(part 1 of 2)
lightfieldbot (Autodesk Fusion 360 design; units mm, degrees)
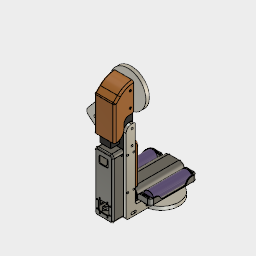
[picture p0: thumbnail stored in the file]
parameter "servohole_1" = 2.8
parameter "d75_1" = 4.75
parameter "d76_1" = 0
parameter "d77_1" = 0
parameter "d78_1" = 0
parameter "d79_1" = 0
parameter "d89_1" = 0
parameter "d90_1" = 0
parameter "d91_1" = 0
parameter "d101_1" = 0
parameter "d102_1" = 0
parameter "d103_1" = 0
parameter "d129_1" = 0
parameter "d130_1" = 0
parameter "d131_1" = 0
parameter "d154_1" = 0
parameter "d155_1" = 0
parameter "d156_1" = 0
parameter "d166_1" = 0
parameter "d167_1" = 0
parameter "d168_1" = 0
parameter "d510" = 25
sketch "Sketch1"
  line L1 (16.7662, -74.21) -> (-16.8338, -74.21)
  line L2 (16.7662, 16.1) -> (16.7662, -74.21)
  line L3 (-16.7662, 16.1) -> (16.7662, 16.1)
  line L4 (-16.7662, -74.21) -> (-16.7662, 16.1)
  line L5 (16.7662, 0) -> (0, 0)
  line L6 (-16.7662, 0) -> (0, 0)
  line L7 (16.7662, -74.21) -> (-16.7662, -74.21)
  line L8 (16.7662, -78.09) -> (16.7662, -74.21)
  line L9 (-16.7662, -78.09) -> (16.7662, -78.09)
  line L10 (-16.7662, -74.21) -> (-16.7662, -78.09)
  circle C1 centre (0, 0) radius 32.5
  circle C2 centre (0, 0) radius 6.325
  point P3 (16.7662, -74.21)
  point P4 (16.7662, 16.1)
  point P2 (-16.8338, -74.21)
  point P1 (0, 0)
  point P7 (-16.7662, -74.21)
  point P14 (-16.7662, -78.09)
  dimension "d1_1" distance P3 P4 = 90.31
  dimension "d2_1" distance P2 P3 = 33.6
  dimension "d3_1" diameter C1 = 65
  dimension "d4_1" distance P1 L1 = 74.21
  dimension "d5_1" distance P7 P14 = 3.88
  dimension "d25_1" diameter C2 = 12.65
  dimension "d93_1" OffsetX = 0
  dimension "d94_1" OffsetY = 0
  dimension "d95_1" OffsetZ = 0
  dimension "d96_1" AngleZ = 0
  dimension "d105_1" OffsetX = 0
  dimension "d106_1" OffsetY = 0
  dimension "d107_1" OffsetZ = 0
  dimension "d108_1" AngleZ = 0
  dimension "d158_1" OffsetX = 0
  dimension "d159_1" OffsetY = 0
  dimension "d160_1" OffsetZ = 0
  dimension "d161_1" AngleZ = 0
extrude "Extrude1" sketch "Sketch1" profile of L1 L2 L3 L4 C1 L7 blind 16.7 named "d6_1"
extrude "Extrude2" sketch "Sketch1" profile of L2 L3 L4 C1 blind -6.4 named "d9_1" from offset -8 named "d8_1"
extrude "Extrude3" sketch "Sketch1" profile of L1 L7 L8 L9 L10 blind 3.25 named "d11_1"
sketch "Sketch2" plane through (0, 0, 16.7) normal (0, 0, 1) x axis (-1, 0, 0)
  line L1 (-16.7662, 74.21) -> (16.7662, 74.21)
  line L2 (-16.7662, -16.1) -> (-16.7662, 74.21)
  line L3 (16.7662, -16.1) -> (-16.7662, -16.1)
  line L4 (16.7662, 74.21) -> (16.7662, -16.1)
  line L5 (-9.8, 68.21) -> (9.8, 68.21)
  line L6 (-9.8, 27.86) -> (-9.8, 68.21)
  line L7 (9.8, 27.86) -> (-9.8, 27.86)
  line L8 (9.8, 68.21) -> (9.8, 27.86)
  line L9 (0, 68.21) -> (0, 74.21)
  line L10 (-6.85, 6.9425) -> (6.85, 6.9425)
  line L11 (-6.85, -6.9075) -> (-6.85, 6.9425)
  line L12 (6.85, -6.9075) -> (-6.85, -6.9075)
  line L13 (6.85, 6.9425) -> (6.85, -6.9075)
  line L14 (0, 0) -> (0, -6.9075)
  point P6 (9.8, 68.21)
  point P7 (-9.8, 68.21)
  point P8 (-9.8, 27.86)
  point P14 (-6.85, -6.9075)
  point P15 (6.85, -6.9075)
  point P13 (-6.85, 6.9425)
  dimension "d13_1" distance P6 P7 = 19.6
  dimension "d14_1" distance P7 P8 = 40.35
  dimension "d15_1" distance L1 L5 = 6
  dimension "d16_1" distance P14 P15 = 13.7
  dimension "d17_1" distance P13 P14 = 13.85
extrude "Extrude4" sketch "Sketch2" profile of L10 L11 L12 L13 blind 13.07 named "d18_1"
extrude "Extrude5" sketch "Sketch2" profile of L5 L6 L7 L8 blind 16.07 named "d20_1"
sketch "Sketch3" plane through (0, 0, -14.4) normal (0, 0, -1) x axis (1, 0, 0)
  circle C1 centre (0, 0) radius 32.5
  circle C2 centre (0, 0) radius 12.65
  dimension "d22_1" diameter C2 = 25.3
extrude "Extrude6" add sketch "Sketch3" profile of C2 along normal blind 6.2 named "d23_1"
extrude "Extrude7" add sketch "Sketch1" profile of C2 to an object
sketch "Sketch4" plane through (-16.7662, 0, 0) normal (-1, 0, 0) x axis (0, -1, 0)
  line L1 (78.09, 0) -> (-16.1, 0)
  line L2 (78.09, 3.25) -> (78.09, 0)
  line L3 (74.21, 3.25) -> (78.09, 3.25)
  line L4 (74.21, 16.7) -> (74.21, 3.25)
  line L5 (-16.1, 16.7) -> (74.21, 16.7)
  line L6 (-16.1, 0) -> (-16.1, 16.7)
  line L7 (74.21, 16.7) -> (-16.1, 16.7)
  circle C1 centre (-13.1, 5.8006) radius 1.4
  circle C2 centre (-13.1, 13.7) radius 1.4
  circle C3 centre (13.8494, 13.7) radius 1.4
  circle C4 centre (13.8494, 5.8006) radius 1.4
  circle C5 centre (70.9994, 5.8006) radius 1.4
  circle C6 centre (70.9994, 13.7) radius 1.4
  circle C7 centre (44.05, 13.7) radius 1.4
  circle C8 centre (44.05, 5.8006) radius 1.4
  point P8 (-13.1, 5.8006)
  point P9 (-13.1, 13.7)
  point P10 (13.8494, 13.7)
  point P11 (13.8494, 5.8006)
  point P14 (44.05, 13.7)
  point P15 (44.05, 5.8006)
  point P12 (70.9994, 13.7)
  point P13 (70.9994, 5.8006)
  dimension "d28_1" diameter C1 = 2.8 (= "servohole_1")
  dimension "d29_1" diameter C2 = 2.8 (= "servohole_1")
  dimension "d31_1" distance P8 P9 = 7.8994
  dimension "d32_1" diameter C4 = 2.8 (= "servohole_1")
  dimension "d33_1" diameter C3 = 2.8 (= "servohole_1")
  dimension "d34_1" distance P10 P11 = 7.8994
  dimension "d35_1" distance P9 P10 = 26.9494
  dimension "d36_1" diameter C8 = 2.8 (= "servohole_1")
  dimension "d37_1" diameter C7 = 2.8 (= "servohole_1")
  dimension "d38_1" distance P14 P15 = 7.8994
  dimension "d39_1" diameter C5 = 2.8 (= "servohole_1")
  dimension "d40_1" diameter C6 = 2.8 (= "servohole_1")
  dimension "d41_1" distance P12 P13 = 7.8994
  dimension "d42_1" distance P12 P14 = 26.9494
  dimension "d43_1" distance P9 P12 = 84.0994
  dimension "d44_1" distance P9 L7 = 3
  dimension "d50_1" distance L6 P9 = 3
extrude "Extrude8" sketch "Sketch4" profile of C1 C2 C3 C4 C5 C6 C7 C8 blind -7 named "d45_1"
extrude "Extrude9" sketch "Sketch4" profile of C1 C2 C3 C4 C5 C6 C7 C8 blind 7 named "d48_1"
joint_origin "JointOrigin5" OffsetX 0 named "d170_1" OffsetY 0 named "d171_1" OffsetZ 0 named "d172_1" AngleZ 0 named "d173_1"
sketch "Sketch2"
  line L1 (-72, 0) -> (0, 0)
  line L2 (-72, 136) -> (-72, 0)
  line L3 (0, 136) -> (-72, 136)
  line L4 (0, 0) -> (0, 136)
  line L5 (-52, 136) -> (0, 136)
  line L6 (-72, 33) -> (-72, 0)
  line L7 (-72, 103) -> (-72, 136)
  line L8 (-52, 103) -> (-72, 103)
  line L9 (-52, 0) -> (-52, 103)
  point P2 (0, 0)
  point P3 (-72, 0)
  point P4 (-72, 136)
  point P8 (-72, 103)
  dimension "d53_1" distance P2 P3 = 72
  dimension "d59_1" distance P4 P8 = 33
  dimension "d60_1" distance L4 L9 = 52
  dimension "d81_1" OffsetX = 0
  dimension "d82_1" OffsetY = 0
  dimension "d83_1" OffsetZ = 0
  dimension "d84_1" AngleZ = 0
  dimension "d72" OffsetX = 0
  dimension "d73" OffsetY = 0
  dimension "d74" OffsetZ = 0
  dimension "d85" AngleZ = 0
extrude "Extrude1" new body sketch "Sketch2" profile of L1 L2 L3 L4 L5 L7 L8 L9 blind 107 named "d57_1"
sketch "Sketch3" plane through (0, 0, 0) normal (0, 0, -1) x axis (1, 0, 0)
  line L1 (-52, 0) -> (0, 0)
  line L2 (-52, -103) -> (-52, 0)
  line L3 (-72, -103) -> (-52, -103)
  line L4 (-72, -136) -> (-72, -103)
  line L5 (0, -136) -> (-72, -136)
  line L6 (0, 0) -> (0, -136)
  circle C1 centre (-18, -53.2) radius 2.5
  point P8 (-18, -53.2)
  dimension "d61_1" diameter C1 = 5
  dimension "d62_1" distance L1 P8 = 53.2
  dimension "d63_1" distance L6 P8 = 18
  dimension "d80_1" AngleZ = 0
  dimension "d92_1" AngleZ = 0
  dimension "d104_1" AngleZ = 0
  dimension "d132_1" AngleZ = 0
  dimension "d157_1" AngleZ = 0
  dimension "d169_1" AngleZ = 0
extrude "Extrude2" cut sketch "Sketch3" profile of C1 against normal blind 12 named "d64_1"
sketch "Sketch4" plane through (-52, 0, 0) normal (-1, 0, 0) x axis (0, -1, 0)
  line L1 (0, 0) -> (-103, 0)
  line L2 (0, 107) -> (0, 0)
  line L3 (-103, 107) -> (0, 107)
  line L4 (-103, 0) -> (-103, 107)
  line L5 (-55.7, 0) -> (-50.7, 0)
  line L6 (-53.2, 42.5) -> (-53.2, 0)
  circle C1 centre (-53.2, 42.5) radius 37.25
  point P6 (-53.2, 42.5)
  dimension "d66_1" distance L1 P6 = 42.5
  dimension "d70_1" diameter C1 = 74.5
extrude "Extrude3" add sketch "Sketch4" profile of C1 along normal blind 95 (= "147 mm - 52 mm") named "d68_1"
copy_paste "CopyPaste1"
sketch "moveplate" plane through (0, -65.568, 162.694) normal (0, 1, 0) x axis (1, 0, 0)
  line L1 (-104, 2.375) -> (-111, 2.375)
  line L2 (-104, -2.375) -> (-22.0772, -2.375)
  line L3 (-122.0642, -15) -> (-122.064, 15)
  line L4 (-22.0772, -2.375) -> (-22.0772, 2.375)
  line L5 (-122.064, 0.9248) -> (-530.5103, 3.462)
  line L6 (-22.0772, 2.375) -> (-104, 2.375)
  line L7 (14.9358, -15) -> (-122.0642, -15)
  line L8 (14.9358, 15) -> (14.9358, -15)
  line L9 (-111, -2.375) -> (-104, -2.375)
  line L10 (-122.064, 15) -> (14.9358, 15)
  line L11 (-22.0772, 2.375) -> (-22.0772, -2.375)
  line L12 (-111, 2.375) -> (-111, -2.375)
  line L13 (-51.3217, -15) -> (-51.3217, -2.375)
  line L14 (-51.3217, 15) -> (-51.3217, 2.375)
  circle C1 centre (0, 0) radius 5.6638
  circle C2 centre (-104, 0) radius 2.375
  circle C3 centre (-6.7633, 7.0631) radius 1.9
  circle C4 centre (-7.0631, -6.7633) radius 1.9
  circle C5 centre (-21.0772, 0) radius 3.5
  circle C6 centre (-111, 0) radius 2.375
  circle C7 centre (7.0631, 6.7633) radius 1.9
  circle C8 centre (6.7633, -7.0631) radius 1.9
  circle C9 centre (11.3218, 11.4852) radius 1.705
  point P6 (-122.064, 15)
  point P7 (-122.0642, -15)
  point P12 (14.9358, -15)
  dimension "d345" distance P6 P7 = 30
  dimension "d347" distance P7 P12 = 137
  dimension "d86" OffsetX = 0
  dimension "d87" OffsetY = 0
  dimension "d88" OffsetZ = 0
  dimension "d97" AngleZ = 0
position "Position5"
extrude "Extrude1" new body sketch "moveplate" profile of L1 L2 L3 L5 L6 C1 L7 L8 L9 L10 C3 C4 C5 C6 C7 C8 C9 along normal blind 4.7625
as_built_joint "As-built1" OffsetX 0 OffsetY 0 OffsetZ 0 AngleZ 0
extrude "Extrude2" new body sketch "moveplate" profile of L5 C2 along normal blind 4.7625
joint "Assemble1" alignAngle 180 alignOffsetX -7 alignOffsetY 0 alignOffsetZ 0
sketch "Sketch1" plane through (0, 3.96, 1.6663) normal (1, 0, 0) x axis (0, -1, 0)
  line L1 (204.0518, 81.0583) -> (184.9318, 81.0583)
  line L2 (204.0518, 108.9983) -> (204.0518, 81.0583)
  line L3 (184.9318, 108.9983) -> (204.0518, 108.9983)
  line L4 (184.9318, 81.0583) -> (184.9318, 108.9983)
extrude "Extrude1" new body sketch "Sketch1" against normal blind 2 named "d247_1_1"
sketch "Sketch2" plane through (0, -200.0918, 0) normal (0, -1, 0) x axis (1, 0, 0)
  line L1 (-8.5, -77.662) -> (-0.5, -77.662)
  line L2 (-8.5, -109.062) -> (-8.5, -77.662)
  line L3 (-0.5, -109.062) -> (-8.5, -109.062)
  line L4 (-0.5, -77.662) -> (-0.5, -109.062)
  line L5 (-0.5, -79.162) -> (-8.5, -79.162)
  line L6 (-0.5, -107.562) -> (-8.5, -107.562)
  line L7 (-2, -79.392) -> (-2, -107.332)
  line L8 (-5.6, -103.562) -> (-5.6, -107.562)
  line L9 (-7.1, -103.562) -> (-5.6, -103.562)
  line L10 (-7.1, -107.562) -> (-7.1, -103.562)
  line L11 (-5.6, -83.162) -> (-5.6, -79.162)
  line L12 (-7.1, -83.162) -> (-5.6, -83.162)
  line L13 (-7.1, -79.162) -> (-7.1, -83.162)
  line L14 (-2, -93.362) -> (-0.5, -93.362)
  line L15 (-2, -107.562) -> (-2, -79.162)
  line L16 (-2, -107.562) -> (-2, -79.162)
  point P13 (-5.6, -107.562)
  point P14 (-5.6, -103.562)
  point P15 (-7.1, -103.562)
  point P17 (-5.6, -79.162)
  point P18 (-5.6, -83.162)
  point P19 (-7.1, -83.162)
  dimension "d261_1_1" distance P13 P14 = 4
  dimension "d262_1_1" distance P14 P15 = 1.5
  dimension "d263_1_1" distance P17 P18 = 4
  dimension "d264_1_1" distance L1 L5 = 1.5
  dimension "d265_1_1" distance L4 L7 = 1.5
  dimension "d266_1_1" distance L3 L6 = 1.5
  dimension "d274_1_1" distance L5 L6 = 28.4
  dimension "d184" distance L11 L15 = 3.6
  dimension "d185" distance P18 P19 = 1.5
  dimension "d186" distance L8 L16 = 3.6
extrude "Extrude4" new body sketch "Sketch2" profile of L4 L5 L6 L7 L15 L16 against normal blind 26 named "d268_1_1"
extrude "Extrude5" add sketch "Sketch2" profile of L1 L2 L3 L4 L5 L6 L7 L8 L9 L10 L11 L12 L13 L15 L16 along normal blind 1.5 named "d270_1_1"
extrude "Extrude13" sketch "Sketch2" profile of L1 L2 L3 L4 L5 L6 blind -10
extrude "Extrude6" add sketch "Sketch2" profile of L5 L6 L8 L9 L10 L11 L12 L13 against normal blind 3 named "d272_1_1"
move "Move1"
sketch "Sketch5" plane through (-147, 0, 0) normal (-1, 0, 0) x axis (0, -1, 0)
  line L1 (123.894, 93.3055) -> (123.894, 28.3055)
  line L2 (165, 42.5) -> (-53.2, 42.5)
  circle C1 centre (-53.2, 42.5) radius 37.25
place_component sketch "Sketch1"
position "Position1"
sketch "Sketch1" plane through (0, 0, 0) normal (1, 0, 0) x axis (0, 1, 0)
  circle C1 centre (50, 25) radius 9.15
  dimension "d110" diameter C1 = 18.3
extrude "Extrude1" sketch "Sketch1" blind 68.5
position "Position2"
sketch "Sketch1" plane through (-16.7662, 0, 0) normal (-1, 0, 0) x axis (0, -1, 0)
  line L1 (67.8625, 91.91) -> (67.8625, 186.1)
  line L2 (71.1125, 91.91) -> (67.8625, 91.91)
  line L3 (71.1125, 95.79) -> (71.1125, 91.91)
  line L4 (84.5625, 95.79) -> (71.1125, 95.79)
  line L5 (84.5625, 186.1) -> (84.5625, 95.79)
  line L6 (67.8625, 186.1) -> (84.5625, 186.1)
  line L7 (89.8625, 134.339) -> (67.8625, 134.339)
  line L8 (89.8625, 0) -> (89.8625, 134.339)
  line L9 (78.09, 0) -> (-16.1, 0)
  line L10 (37.607, 0) -> (89.8625, 0)
  line L11 (27.86, 16.7) -> (68.21, 16.7)
  line L12 (37.607, 16.7) -> (37.607, 0)
  line L13 (68.21, 16.7) -> (27.86, 16.7)
  line L14 (67.8625, 134.339) -> (67.8625, 16.7)
  circle C1 centre (81.5625, 99.0006) radius 1.4
  circle C2 centre (73.6631, 156.1506) radius 1.4
  circle C3 centre (73.6631, 125.95) radius 1.4
  circle C4 centre (81.5625, 125.95) radius 1.4
  circle C5 centre (81.5625, 156.1506) radius 1.4
  circle C6 centre (81.5625, 183.1) radius 1.4
  circle C7 centre (73.6631, 99.0006) radius 1.4
  circle C8 centre (73.6631, 183.1) radius 1.4
  point P16 (67.8625, 134.339)
  point P17 (89.8625, 134.339)
  dimension "d113" distance P16 P17 = 22
sketch "screen" plane through (0, -100.6325, 0) normal (0, -1, 0) x axis (1, 0, 0)
  line L1 (-9.8, 101.79) -> (-9.8, 142.14)
  line L2 (9.8, 101.79) -> (-9.8, 101.79)
  line L3 (9.8, 142.14) -> (9.8, 101.79)
  line L4 (-9.8, 142.14) -> (9.8, 142.14)
  line L5 (16.7662, 89.5884) -> (-16.7662, 89.5884)
  line L6 (16.7662, 49.5884) -> (16.7662, 89.5884)
  line L7 (-13.3, 49.5884) -> (13.3, 49.5884)
  line L8 (-16.7662, 89.5884) -> (-16.7662, 49.5884)
  line L9 (-16.7662, 134.339) -> (-16.7662, 16.7)
  line L10 (-16.7662, 0) -> (-16.7662, 134.339)
  line L11 (8.25, 79.9384) -> (-8.25, 79.9384)
  line L12 (8.25, 66.4384) -> (8.25, 79.9384)
  line L13 (-8.25, 66.4384) -> (8.25, 66.4384)
  line L14 (-8.25, 79.9384) -> (-8.25, 66.4384)
  line L15 (0, 89.5884) -> (0, 79.9384)
  line L16 (16.7662, 95.79) -> (16.7662, 91.91)
  line L17 (16.7662, 87.5884) -> (16.7662, 89.5884)
  line L18 (-16.7662, 87.5884) -> (16.7662, 87.5884)
  line L19 (-13.3, 49.5884) -> (-13.3, 87.5884)
  line L20 (13.3, 87.5884) -> (13.3, 49.5884)
  line L21 (13.3, 49.5884) -> (16.7662, 49.5884)
  line L22 (-16.7662, 49.5884) -> (-13.3, 49.5884)
  line L23 (13.3, 52.6384) -> (-13.3, 52.6384)
  line L24 (9.3, 52.6384) -> (13.3, 52.6384)
  line L25 (9.3, 56.1384) -> (9.3, 52.6384)
  line L26 (13.3, 56.1384) -> (9.3, 56.1384)
  line L27 (-9.3, 52.6384) -> (-13.3, 52.6384)
  line L28 (-9.3, 56.1384) -> (-9.3, 52.6384)
  line L29 (-13.3, 56.1384) -> (-9.3, 56.1384)
  line L30 (9.3, 87.5884) -> (13.3, 87.5884)
  line L31 (9.3, 84.0884) -> (9.3, 87.5884)
  line L32 (13.3, 84.0884) -> (9.3, 84.0884)
  line L33 (-9.3, 87.5884) -> (-13.3, 87.5884)
  line L34 (-9.3, 84.0884) -> (-9.3, 87.5884)
  line L35 (-13.3, 84.0884) -> (-9.3, 84.0884)
  point P14 (-8.25, 79.9384)
  point P15 (8.25, 79.9384)
  point P16 (8.25, 66.4384)
  point P7 (16.7662, 89.5884)
  point P22 (16.7662, 87.5884)
  point P8 (16.7662, 49.5884)
  point P29 (13.3, 52.6384)
  point P30 (9.3, 52.6384)
  point P31 (9.3, 56.1384)
  point P28 (-13.3, 52.6384)
  point P33 (-9.3, 52.6384)
  point P34 (-9.3, 56.1384)
  point P27 (13.3, 87.5884)
  point P36 (9.3, 87.5884)
  point P37 (9.3, 84.0884)
  point P24 (-13.3, 87.5884)
  point P39 (-9.3, 87.5884)
  point P40 (-9.3, 84.0884)
  dimension "d114" distance P14 P15 = 16.5
  dimension "d115" distance P15 P16 = 13.5
  dimension "d116" distance L5 L11 = 9.65
  dimension "d117" distance P7 P22 = 2
  dimension "d118" distance L19 L20 = 26.6
  dimension "d119" distance L18 L23 = 34.95
  dimension "d120" distance P7 P8 = 40
  dimension "d121" distance P29 P30 = 4
  dimension "d122" distance P30 P31 = 3.5
  dimension "d123" distance P28 P33 = 4
  dimension "d124" distance P33 P34 = 3.5
  dimension "d139" distance P27 P36 = 4
  dimension "d140" distance P36 P37 = 3.5
  dimension "d141" distance P24 P39 = 4
  dimension "d142" distance P39 P40 = 3.5
extrude "Extrude7" new body sketch "screen" profile of L5 L6 L7 L8 L9 L10 L11 L12 L13 L14 L17 L18 L19 L20 L21 L22 L23 L24 L25 L26 L27 L28 L29 along normal blind 1.5
extrude "Extrude8" add sketch "screen" profile of L5 L6 L8 L9 L10 L17 L18 L19 L20 L21 L22 against normal blind 20
extrude "Extrude9" add sketch "screen" profile of L19 L20 L23 L24 L25 L26 L27 L28 L29 against normal blind 2.7
extrude "Extrude10" add sketch "screen" profile of L18 L19 L20 L30 L31 L32 L33 L34 L35 blind 5 from offset -12.3 (= "-2.70 mm - 9.6 mm")
chamfer "Chamfer1" distance 4
sketch "sceen side" plane through (13.3, 0, 0) normal (-1, 0, 0) x axis (0, -1, 0)
  line L1 (88.3325, 87.5884) -> (88.3325, 84.0884)
  line L2 (80.6325, 87.5884) -> (88.3325, 87.5884)
  line L3 (80.6325, 49.5884) -> (80.6325, 87.5884)
  line L4 (100.6325, 49.5884) -> (80.6325, 49.5884)
  line L5 (100.6325, 52.6384) -> (100.6325, 49.5884)
  line L6 (97.9325, 52.6384) -> (100.6325, 52.6384)
  line L7 (97.9325, 56.1384) -> (97.9325, 52.6384)
  line L8 (100.6325, 56.1384) -> (97.9325, 56.1384)
  line L9 (100.6325, 87.5884) -> (100.6325, 56.1384)
  line L10 (93.3325, 87.5884) -> (100.6325, 87.5884)
  line L11 (93.3325, 84.0884) -> (93.3325, 87.5884)
  line L12 (88.3325, 84.0884) -> (93.3325, 84.0884)
  line L13 (96.9325, 54.3884) -> (97.9325, 54.3884)
  line L14 (96.9325, 56.7884) -> (96.9325, 54.3884)
  line L15 (94.5, 56.7884) -> (96.9325, 56.7884)
  line L16 (95.4625, 56.7884) -> (96.9325, 56.7884)
  line L17 (96.9325, 55.3184) -> (96.9325, 56.7884)
  line L18 (87.3325, 87.5884) -> (88.3325, 87.5884)
  line L19 (87.3325, 81.3584) -> (87.3325, 87.5884)
  line L20 (85.8625, 81.3584) -> (87.3325, 81.3584)
  line L21 (87.3325, 82.8284) -> (87.3325, 81.3584)
  line L22 (85.8213, -7.1715) -> (85.8625, 82.8284)
  circle C1 centre (95.4625, 55.3184) radius 1.47
  circle C2 centre (85.8625, 82.8284) radius 1.47
  circle C3 centre (85.8213, -7.1715) radius 1.47
  point P14 (97.9325, 54.3884)
  point P15 (96.9325, 54.3884)
  point P16 (96.9325, 56.7884)
  point P18 (95.4625, 56.7884)
  point P19 (96.9325, 55.3184)
  point P21 (88.3325, 87.5884)
  point P22 (87.3325, 87.5884)
  point P23 (87.3325, 81.3584)
  point P24 (85.8625, 81.3584)
  point P25 (87.3325, 82.8284)
  point P27 (85.8625, 82.8284)
  point P28 (85.8213, -7.1715)
  point P26 (85.8625, 82.8284)
  dimension "d147" distance P14 P15 = 1
  dimension "d148" distance L4 L15 = 7.2
  dimension "d149" distance P16 P18 = 1.47
  dimension "d150" distance P16 P19 = 1.47
  dimension "d300" distance P21 P22 = 1
  dimension "d301" distance P22 P23 = 6.23
  dimension "d302" distance P23 P24 = 1.47
  dimension "d303" distance P23 P25 = 1.47
  dimension "d308" distance P27 P28 = 90
  dimension "d309" diameter C3 = 2.94 (= "( 1.47 * 2 ) * 1 mm")
  dimension "d310" distance L9 P26 = 14.77
extrude "Extrude11" cut sketch "sceen side" profile of C1 along normal blind 32 and against normal blind 5
sketch "Sketch5" plane through (26.2608, 0, 0) normal (-1, 0, 0) x axis (0, -1, 0)
  line L1 (148.0461, 70.838) -> (148.0461, 42.438)
  line L2 (122.0461, 70.838) -> (138.0461, 70.838)
  line L3 (122.0461, 42.438) -> (122.0461, 70.838)
  line L4 (138.0461, 42.438) -> (122.0461, 42.438)
  line L5 (128.5461, 56.638) -> (148.0461, 56.638)
  line L6 (138.0461, 70.838) -> (148.0461, 70.838)
  line L7 (148.0461, 42.438) -> (138.0461, 42.438)
  line L8 (148.4942, 59.638) -> (122.0461, 59.638)
  line L9 (148.0461, 53.638) -> (122.0461, 53.638)
  circle C1 centre (127.0761, 56.638) radius 1.47
  point P6 (148.0461, 56.638)
  point P7 (128.5461, 56.638)
  point P8 (127.0761, 56.638)
  dimension "d179" distance P6 P7 = 19.5
  dimension "d180" diameter C1 = 2.94
  dimension "d236" distance P8 L8 = 3
  dimension "d237" distance P8 L9 = 3 (= "d236")
extrude "Extrude12" cut sketch "Sketch5" profile of C1 against normal blind 3
position "Position3" RotateAboutZ -67.5
sketch "joy1" plane through (0, -102.1325, 0) normal (0, -1, 0) x axis (1, 0, 0)
  line L1 (-8.25, 66.4384) -> (8.25, 66.4384)
  line L2 (-8.25, 79.9384) -> (-8.25, 66.4384)
  line L3 (8.25, 79.9384) -> (-8.25, 79.9384)
  line L4 (8.25, 66.4384) -> (8.25, 79.9384)
  line L5 (-16.7662, 49.5884) -> (-16.7662, 89.5884)
  line L6 (16.7662, 49.5884) -> (-16.7662, 49.5884)
  line L7 (16.7662, 89.5884) -> (16.7662, 49.5884)
  line L8 (-16.7662, 89.5884) -> (16.7662, 89.5884)
  line L9 (16.7662, 16.5884) -> (-16.7662, 16.5884)
  line L10 (16.7662, -15.4116) -> (16.7662, 16.5884)
  line L11 (-16.7662, -15.4116) -> (16.7662, -15.4116)
  line L12 (-16.7662, 16.5884) -> (-16.7662, -15.4116)
  line L13 (14.7662, 16.5884) -> (16.7662, 16.5884)
  line L14 (14.7662, -15.4116) -> (14.7662, 16.5884)
  line L15 (-14.7662, -15.4116) -> (-14.7662, 16.5884)
  line L16 (0, -15.4116) -> (0, 16.5884)
  line L17 (-14.7662, 1.5884) -> (14.6773, 1.5884)
  line L18 (5.86, 10.4884) -> (5.86, 16.5884)
  line L19 (14.7662, 10.4884) -> (5.86, 10.4884)
  line L20 (-7.83, 10.4884) -> (-7.83, 16.5884)
  line L21 (-14.7662, 10.4884) -> (-7.83, 10.4884)
  line L22 (-7.83, -9.5116) -> (-14.7662, -9.5116)
  line L23 (-7.83, -15.4116) -> (-7.83, -9.5116)
  line L24 (5.86, -9.5116) -> (14.7662, -9.5116)
  line L25 (5.86, -15.4116) -> (5.86, -9.5116)
  line L26 (-10.83, -12.5116) -> (8.86, -12.5116)
  line L27 (-10.83, 13.4884) -> (-10.83, -12.5116)
  line L28 (8.86, 13.4884) -> (-10.83, 13.4884)
  line L29 (8.86, -12.5116) -> (8.86, 13.4884)
  line L30 (-9.5, 10.6884) -> (9.5, 10.6884)
  line L31 (-9.5, -8.3116) -> (-9.5, 10.6884)
  line L32 (9.5, -8.3116) -> (-9.5, -8.3116)
  line L33 (9.5, 10.6884) -> (9.5, -8.3116)
  line L34 (-2, 1.1884) -> (-9.5, 1.1884)
  circle C1 centre (8.86, 13.4884) radius 1.55
  circle C2 centre (-10.83, -12.5116) radius 1.55
  circle C3 centre (-10.83, 13.4884) radius 1.55
  circle C4 centre (8.86, -12.5116) radius 1.55
  circle C5 centre (11.5662, 8.8384) radius 1.25
  circle C6 centre (11.5662, -5.6616) radius 1.25
  circle C7 centre (-11.5662, 8.8384) radius 1.25
  circle C8 centre (-11.5662, -5.6616) radius 1.25
  circle C9 centre (6.85, 12.6884) radius 1.25
  circle C10 centre (-6.85, 12.6884) radius 1.25
  circle C11 centre (6.85, -10.3116) radius 1.25
  circle C12 centre (-6.85, -10.3116) radius 1.25
  point P11 (16.7662, 16.5884)
  point P12 (16.7662, -15.4116)
  point P18 (8.86, 13.4884)
  point P19 (-10.83, -12.5116)
  point P24 (-10.83, 13.4884)
  point P25 (8.86, -12.5116)
  point P43 (-9.5, 10.6884)
  point P44 (-9.5, -8.3116)
  point P42 (9.5, 10.6884)
  point P51 (-11.5662, -5.6616)
  point P13 (-16.7662, -15.4116)
  point P52 (6.85, 12.6884)
  dimension "d190" distance P11 P12 = 32
  dimension "d191" distance L10 L14 = 2
  dimension "d192" distance L12 L15 = 2
  dimension "d193" diameter C1 = 3.1
  dimension "d194" diameter C2 = 3.1
  dimension "d195" distance P18 L16 = 8.86
  dimension "d197" distance P18 P19 = 19.69
  dimension "d198" distance P18 L17 = 11.9
  dimension "d199" distance P18 P19 = 26
  dimension "d205" diameter C3 = 3.1
  dimension "d206" diameter C4 = 3.1
  dimension "d207" distance P18 L18 = 3
  dimension "d208" distance P18 L19 = 3
  dimension "d209" distance P24 L20 = 3
  dimension "d210" distance P24 L21 = 3
  dimension "d211" distance P19 L22 = 3
  dimension "d213" distance P25 L25 = 3
  dimension "d214" distance P25 L24 = 3
  dimension "d222" distance P43 P44 = 19
  dimension "d223" distance P42 P43 = 19
  dimension "d230" diameter C5 = 2.5
  dimension "d240" distance L9 P24 = 3.1
  dimension "d241" distance L9 L30 = 5.9
  dimension "d244" distance L15 P51 = 3.2
  dimension "d245" distance P12 P13 = 33.5323
  dimension "d246" distance L22 P51 = 3.85
  dimension "d247" distance L6 L9 = 33
  dimension "d447" diameter C9 = 2.5
  dimension "d448" distance L30 P52 = 2
  dimension "d449" distance L33 P52 = 2.65
extrude "Extrude14" new body sketch "joy1" profile of L9 L10 L11 L12 L13 L14 L15 C1 C2 against normal blind 1.5
extrude "Extrude15" add sketch "joy1" profile of L9 L10 L11 L12 L13 L14 L15 against normal blind 19
sketch "joy2" plane through (14.7662, 0, 0) normal (-1, 0, 0) x axis (0, -1, 0)
  line L1 (100.6325, 16.5884) -> (100.6325, -15.4116)
  line L2 (83.1325, 16.5884) -> (100.6325, 16.5884)
  line L3 (83.1325, -15.4116) -> (83.1325, 16.5884)
  line L4 (100.6325, -15.4116) -> (83.1325, -15.4116)
extrude "Extrude17" cut sketch "joy1" profile of C1 C3 L18 L19 L20 L21 L30 L31 L32 L33 against normal blind 13
extrude "Extrude16" add sketch "joy1" profile of L9 L11 L14 L15 C1 C2 C3 C4 L18 L19 L20 L21 L22 L23 L24 L25 L30 L31 L33 blind 1.5 from offset -18.5 (= "-17 mm - 1.5 mm")
fillet "Fillet1" radius 3
extrude "Extrude19" cut sketch "joy1" profile of C5 C6 C7 C8 C9 C10 C11 C12 against normal blind 5
chamfer "Chamfer4" distance 2.5
extrude "Extrude20" of existing geometry blind -1.7
sketch "csr" plane through (0, -102.1325, 0) normal (0, -1, 0) x axis (1, 0, 0)
  line L1 (16.7662, 49.5884) -> (-16.7662, 49.5884)
  line L2 (16.7662, 16.5884) -> (-16.7662, 16.5884)
  line L3 (-16.7662, 16.5884) -> (-16.7662, 49.5884)
  line L4 (16.7662, 16.5884) -> (16.7662, 49.5884)
  line L5 (13.3, 16.5884) -> (13.3, 49.5884)
  line L6 (-13.3, 52.6384) -> (-13.3, 49.5884)
  line L7 (-13.3, 16.5884) -> (-13.3, 49.5884)
  line L8 (13.3, 18.5884) -> (13.3, 46.1574)
  line L9 (-13.3, 18.5884) -> (13.3, 18.5884)
  line L10 (-13.3, 16.5884) -> (13.3, 16.5884)
  line L11 (13.3, 19.5884) -> (-13.3, 19.5884)
  line L12 (13.3, 47.9884) -> (-13.3, 47.9884)
  line L13 (13.3, 48.9884) -> (-13.3, 48.9884)
  line L14 (9.7, 47.9884) -> (13.3, 47.9884)
  line L15 (9.7, 43.9884) -> (9.7, 47.9884)
  line L16 (8.2, 43.9884) -> (9.7, 43.9884)
  line L17 (8.2, 47.9884) -> (8.2, 43.9884)
  line L18 (9.7, 19.5884) -> (13.3, 19.5884)
  line L19 (9.7, 23.5884) -> (9.7, 19.5884)
  line L20 (8.2, 23.5884) -> (9.7, 23.5884)
  line L21 (8.2, 19.5884) -> (8.2, 23.5884)
  line L22 (9.7, 23.5884) -> (9.7, 43.9884)
  line L23 (13.3, 43.9884) -> (9.7, 43.9884)
  line L24 (8.2, 48.9884) -> (8.2, 47.9884)
  line L25 (13.3, 23.5884) -> (9.7, 23.5884)
  line L26 (8.2, 18.5884) -> (8.2, 19.5884)
  point P23 (13.3, 47.9884)
  point P26 (9.7, 47.9884)
  point P27 (9.7, 43.9884)
  point P28 (8.2, 43.9884)
  point P21 (13.3, 19.5884)
  point P30 (9.7, 19.5884)
  point P31 (9.7, 23.5884)
  point P32 (8.2, 23.5884)
  dimension "d256" distance L9 L10 = 2
  dimension "d261" distance L9 L11 = 1
  dimension "d262" distance L11 L12 = 28.4
  dimension "d263" distance L12 L13 = 1
  dimension "d264" distance P23 P26 = 3.6
  dimension "d265" distance P26 P27 = 4
  dimension "d266" distance P27 P28 = 1.5
  dimension "d267" distance P21 P30 = 3.6
  dimension "d268" distance P30 P31 = 4
  dimension "d269" distance P31 P32 = 1.5
extrude "Extrude23" add sketch "csr" profile of L1 L2 L3 L4 L5 L7 L8 against normal blind 21.5
extrude "Extrude24" add sketch "csr" profile of L1 L2 L5 L7 L8 L9 L10 against normal blind 1.5
extrude "Extrude25" add sketch "csr" profile of L5 L8 L11 L12 L14 L15 L18 L19 L23 L25 against normal blind 2
extrude "Extrude26" new body sketch "csr" profile of L5 L8 L9 L11 L12 L13 L14 L15 L16 L17 L18 L19 L20 L21 L24 L26 against normal blind 4
sketch "Sketch9" plane through (13.3, 0, 0) normal (-1, 0, 0) x axis (0, -1, 0)
  line L1 (100.6325, 23.5884) -> (100.1325, 23.5884)
  line L2 (100.6325, 43.9884) -> (100.6325, 23.5884)
  line L3 (100.1325, 43.9884) -> (100.6325, 43.9884)
  line L4 (100.1325, 47.9884) -> (100.1325, 43.9884)
  line L5 (100.6325, 47.9884) -> (100.1325, 47.9884)
  line L6 (100.6325, 52.6384) -> (100.6325, 47.9884)
  line L7 (97.9325, 52.6384) -> (100.6325, 52.6384)
  line L8 (97.9325, 56.1384) -> (97.9325, 52.6384)
  line L9 (100.6325, 56.1384) -> (97.9325, 56.1384)
  line L10 (100.6325, 87.5884) -> (100.6325, 56.1384)
  line L11 (93.3325, 87.5884) -> (100.6325, 87.5884)
  line L12 (93.3325, 84.0884) -> (93.3325, 87.5884)
  line L13 (88.3325, 84.0884) -> (93.3325, 84.0884)
  line L14 (88.3325, 87.5884) -> (88.3325, 84.0884)
  line L15 (80.6325, 87.5884) -> (88.3325, 87.5884)
  line L16 (80.6325, 16.5884) -> (80.6325, 87.5884)
  line L17 (83.6325, 16.5884) -> (80.6325, 16.5884)
  line L18 (85.1325, 16.5884) -> (83.6325, 16.5884)
  line L19 (100.6325, 16.5884) -> (85.1325, 16.5884)
  line L20 (100.6325, 19.5884) -> (100.6325, 16.5884)
  line L21 (100.1325, 19.5884) -> (100.6325, 19.5884)
  line L22 (100.1325, 23.5884) -> (100.1325, 19.5884)
  line L23 (100.1325, 43.9884) -> (100.1325, 23.5884)
  line L24 (79.1625, 33.7884) -> (100.1325, 33.7884)
  circle C1 centre (79.1625, 33.7884) radius 1.47
  point P28 (100.1325, 33.7884)
  point P29 (79.1625, 33.7884)
  dimension "d274" distance P28 P29 = 20.97
  dimension "d275" diameter C1 = 2.94
extrude "Extrude27" add of existing geometry blind 3.5
extrude "Extrude28" cut sketch "Sketch9" profile of C1 against normal blind 8
extrude "Extrude29" add of existing geometry blind 6
extrude "Extrude21" add sketch "csr" profile of L1 L2 L3 L4 L5 L7 against normal blind 21.5
extrude "Extrude22" sketch "csr" profile of L1 L2 L5 L7 blind -1.5
fillet "Fillet2" radius 2
extrude "Extrude30" of existing geometry blind 1.466
extrude "Extrude31" add of existing geometry blind 1.466
chamfer "Chamfer5" distance 7.4
chamfer "Chamfer6" distance 5.45
extrude "Extrude18" cut sketch "joy1" profile of C1 C2 C3 C4 L30 L31 blind -30 from offset -5
extrude "Extrude32" cut of existing geometry blind -0.04
extrude "Extrude33" cut of existing geometry blind -0.04
extrude "Extrude34" new body sketch "csr" profile of L5 L8 L9 L11 L12 L13 L14 L18 L24 L26 against normal blind 6
combine "Combine1"
extrude "Extrude35" cut of existing geometry blind -0.15
sketch "Sketch10" plane through (0, -100.6325, 0) normal (0, 1, 0) x axis (-1, 0, 0)
  line L1 (6.5, 10.6884) -> (-6.5, 10.6884)
  line L2 (9.5, -5.3116) -> (9.5, 7.6884)
  line L3 (-6.5, -8.3116) -> (6.5, -8.3116)
  line L4 (-9.5, 7.6884) -> (-9.5, -5.3116)
  line L5 (-8.25, 77.9384) -> (-8.25, 68.4384)
  line L6 (6.25, 79.9384) -> (-6.25, 79.9384)
  line L7 (8.25, 68.4384) -> (8.25, 77.9384)
  line L8 (-6.25, 66.4384) -> (6.25, 66.4384)
  line L9 (-8.2, 23.5884) -> (-13.3, 23.5884)
  line L10 (-8.2, 18.5884) -> (-8.2, 23.5884)
  line L11 (-13.3, 18.5884) -> (-8.2, 18.5884)
  line L12 (-13.3, 16.5884) -> (-13.3, 18.5884)
  line L13 (-13.3002, 16.5884) -> (-13.3, 16.5884)
  line L14 (-13.3002, -15.4116) -> (-13.3002, 16.5884)
  line L15 (13.3002, -15.4116) -> (-13.3002, -15.4116)
  line L16 (13.3002, 16.5884) -> (13.3002, -15.4116)
  line L17 (13.3, 16.5884) -> (13.3002, 16.5884)
  line L18 (13.3, 52.7884) -> (13.3, 16.5884)
  line L19 (9.3, 52.7884) -> (13.3, 52.7884)
  line L20 (9.3, 56.1384) -> (9.3, 52.7884)
  line L21 (13.3, 56.1384) -> (9.3, 56.1384)
  line L22 (13.3, 87.5884) -> (13.3, 56.1384)
  line L23 (-13.3, 87.5884) -> (13.3, 87.5884)
  line L24 (-13.3, 56.1384) -> (-13.3, 87.5884)
  line L25 (-9.3, 56.1384) -> (-13.3, 56.1384)
  line L26 (-9.3, 52.7884) -> (-9.3, 56.1384)
  line L27 (-13.3, 52.7884) -> (-9.3, 52.7884)
  line L28 (-13.3, 48.9884) -> (-13.3, 52.7884)
  line L29 (-8.2, 48.9884) -> (-13.3, 48.9884)
  line L30 (-8.2, 43.9884) -> (-8.2, 48.9884)
  line L31 (-13.3, 43.9884) -> (-8.2, 43.9884)
  line L32 (-13.3, 23.5884) -> (-13.3, 43.9884)
  line L33 (13.3, 51.4993) -> (-13.3, 51.4993)
  line L34 (-9.3, 51.4993) -> (-9.3, 52.7884)
  line L35 (9.3, 51.4993) -> (9.3, 52.7884)
  arc A1 centre (6.5, 7.6884) radius 3 clockwise from (6.5, 10.6884) to (9.5, 7.6884)
  arc A2 centre (6.5, -5.3116) radius 3 clockwise from (9.5, -5.3116) to (6.5, -8.3116)
  arc A3 centre (-6.5, -5.3116) radius 3 clockwise from (-6.5, -8.3116) to (-9.5, -5.3116)
  arc A4 centre (-6.5, 7.6884) radius 3 clockwise from (-9.5, 7.6884) to (-6.5, 10.6884)
  circle C1 centre (11.5662, -5.6616) radius 1.25
  circle C2 centre (-11.5662, 8.8384) radius 1.25
  circle C3 centre (11.5662, 8.8384) radius 1.25
  circle C4 centre (-11.5662, -5.6616) radius 1.25
  arc A5 centre (-6.25, 68.4384) radius 2 clockwise from (-6.25, 66.4384) to (-8.25, 68.4384)
  arc A6 centre (-6.25, 77.9384) radius 2 clockwise from (-8.25, 77.9384) to (-6.25, 79.9384)
  arc A7 centre (6.25, 77.9384) radius 2 clockwise from (6.25, 79.9384) to (8.25, 77.9384)
  arc A8 centre (6.25, 68.4384) radius 2 clockwise from (8.25, 68.4384) to (6.25, 66.4384)
  circle C5 centre (-6.85, -10.3116) radius 1.25
  circle C6 centre (6.85, 12.6884) radius 1.25
  circle C7 centre (6.85, -10.3116) radius 1.25
  circle C8 centre (-6.85, 12.6884) radius 1.25
extrude "Extrude36" add sketch "Sketch10" profile of L18 L19 L27 L28 L33 L34 L35 along normal blind 4.7
extrude "Extrude37" cut sketch "sceen side" profile of C2 along normal blind 32 and against normal blind 5
extrude "Extrude38" cut sketch "sceen side" profile of C3 along normal blind 35 and against normal blind 6
sketch "Sketch11" plane through (0, 0, -15.4116) normal (0, 0, -1) x axis (1, 0, 0)
  line L1 (16.7262, 102.1325) -> (16.7262, 77.1325)
  line L2 (-16.7262, 102.1325) -> (16.7262, 102.1325)
  line L3 (-16.7262, 77.1325) -> (-16.7262, 102.1325)
  line L4 (-13.3002, 77.1325) -> (-16.7262, 77.1325)
  line L5 (-13.3002, 83.6325) -> (-13.3002, 77.1325)
  line L6 (-7.83, 83.6325) -> (-13.3002, 83.6325)
  line L7 (-7.83, 85.1325) -> (-7.83, 83.6325)
  line L8 (-7.8502, 85.1325) -> (-7.83, 85.1325)
  line L9 (-13.3002, 90.5825) -> (-7.8502, 85.1325)
  line L10 (-13.3002, 100.6325) -> (-13.3002, 90.5825)
  line L11 (13.3002, 100.6325) -> (-13.3002, 100.6325)
  line L12 (13.3002, 92.5325) -> (13.3002, 100.6325)
  line L13 (5.9002, 85.1325) -> (13.3002, 92.5325)
  line L14 (5.86, 85.1325) -> (5.9002, 85.1325)
  line L15 (5.86, 83.6325) -> (5.86, 85.1325)
  line L16 (13.3002, 83.6325) -> (5.86, 83.6325)
  line L17 (13.3002, 77.1325) -> (13.3002, 83.6325)
  line L18 (16.7262, 77.1325) -> (13.3002, 77.1325)
  line L19 (-16.7662, 100.6325) -> (-13.3002, 100.6325)
  line L20 (16.7662, 100.6325) -> (13.3002, 100.6325)
extrude "Extrude39" add sketch "Sketch11" profile of L1 L2 L3 L11 L19 L20 along normal blind 2
sketch "Sketch12" plane through (0, -100.6325, 0) normal (0, 1, 0) x axis (-1, 0, 0)
  line L1 (6.5, 10.6884) -> (-6.5, 10.6884)
  line L2 (9.5, -5.3116) -> (9.5, 7.6884)
  line L3 (-6.5, -8.3116) -> (6.5, -8.3116)
  line L4 (-9.5, 7.6884) -> (-9.5, -5.3116)
  line L5 (-8.25, 77.9384) -> (-8.25, 68.4384)
  line L6 (6.25, 79.9384) -> (-6.25, 79.9384)
  line L7 (8.25, 68.4384) -> (8.25, 77.9384)
  line L8 (-6.25, 66.4384) -> (6.25, 66.4384)
  line L9 (9.3, 51.4993) -> (13.3, 51.4993)
  line L10 (9.3, 56.1384) -> (9.3, 51.4993)
  line L11 (13.3, 56.1384) -> (9.3, 56.1384)
  line L12 (13.3, 87.5884) -> (13.3, 56.1384)
  line L13 (-13.3, 87.5884) -> (13.3, 87.5884)
  line L14 (-13.3, 56.1384) -> (-13.3, 87.5884)
  line L15 (-9.3, 56.1384) -> (-13.3, 56.1384)
  line L16 (-9.3, 51.4993) -> (-9.3, 56.1384)
  line L17 (-13.3, 51.4993) -> (-9.3, 51.4993)
  line L18 (-13.3, 48.9884) -> (-13.3, 51.4993)
  line L19 (-8.2, 48.9884) -> (-13.3, 48.9884)
  line L20 (-8.2, 43.9884) -> (-8.2, 48.9884)
  line L21 (-13.3, 43.9884) -> (-8.2, 43.9884)
  line L22 (-13.3, 23.5884) -> (-13.3, 43.9884)
  line L23 (-8.2, 23.5884) -> (-13.3, 23.5884)
  line L24 (-8.2, 18.5884) -> (-8.2, 23.5884)
  line L25 (-13.3, 18.5884) -> (-8.2, 18.5884)
  line L26 (-13.3, 16.5884) -> (-13.3, 18.5884)
  line L27 (-13.3002, 16.5884) -> (-13.3, 16.5884)
  line L28 (-13.3002, -15.4116) -> (-13.3002, 16.5884)
  line L29 (-16.7262, -17.4116) -> (-16.7262, -15.4116)
  line L30 (16.7262, -17.4116) -> (-16.7262, -17.4116)
  line L31 (16.7262, -15.4116) -> (16.7262, -17.4116)
  line L32 (13.3002, -15.4116) -> (16.7262, -15.4116)
  line L33 (13.3002, 16.5884) -> (13.3002, -15.4116)
  line L34 (13.3, 16.5884) -> (13.3002, 16.5884)
  line L35 (13.3, 51.4993) -> (13.3, 16.5884)
  line L36 (16.7262, -15.6616) -> (-16.7262, -15.6616)
  line L37 (13.3002, -15.6616) -> (13.3002, -15.4116)
  line L38 (-13.3002, -15.6616) -> (-13.3002, -15.4116)
  line L39 (-16.7262, -15.4116) -> (-13.3002, -15.4116)
  arc A1 centre (6.5, 7.6884) radius 3 clockwise from (6.5, 10.6884) to (9.5, 7.6884)
  arc A2 centre (6.5, -5.3116) radius 3 clockwise from (9.5, -5.3116) to (6.5, -8.3116)
  arc A3 centre (-6.5, -5.3116) radius 3 clockwise from (-6.5, -8.3116) to (-9.5, -5.3116)
  arc A4 centre (-6.5, 7.6884) radius 3 clockwise from (-9.5, 7.6884) to (-6.5, 10.6884)
  circle C1 centre (11.5662, -5.6616) radius 1.25
  circle C2 centre (-11.5662, 8.8384) radius 1.25
  circle C3 centre (11.5662, 8.8384) radius 1.25
  circle C4 centre (-11.5662, -5.6616) radius 1.25
  arc A5 centre (-6.25, 68.4384) radius 2 clockwise from (-6.25, 66.4384) to (-8.25, 68.4384)
  arc A6 centre (-6.25, 77.9384) radius 2 clockwise from (-8.25, 77.9384) to (-6.25, 79.9384)
  arc A7 centre (6.25, 77.9384) radius 2 clockwise from (6.25, 79.9384) to (8.25, 77.9384)
  arc A8 centre (6.25, 68.4384) radius 2 clockwise from (8.25, 68.4384) to (6.25, 66.4384)
  circle C5 centre (-6.85, -10.3116) radius 1.25
  circle C6 centre (6.85, 12.6884) radius 1.25
  circle C7 centre (6.85, -10.3116) radius 1.25
  circle C8 centre (-6.85, 12.6884) radius 1.25
  dimension "d322" distance L30 L36 = 1.75
extrude "Extrude40" add sketch "Sketch12" profile of L29 L30 L31 L36 against normal blind 1.5
extrude "Extrude41" add sketch "Sketch12" profile of L29 L30 L31 L32 L36 L37 L38 L39 along normal blind 23.5
fillet "Fillet5" radius 5
fillet "Fillet6" radius 2.5
sketch "Sketch13" plane through (0, -77.1325, 0) normal (0, 1, 0) x axis (-1, 0, 0)
  line L1 (-16.7262, -12.4116) -> (-16.7262, 84.5884)
  line L2 (11.7262, -17.4116) -> (-11.7262, -17.4116)
  line L3 (16.7262, 84.5884) -> (16.7262, -12.4116)
  line L4 (-11.7262, 89.5884) -> (11.7262, 89.5884)
  line L5 (13.3002, -15.6616) -> (13.3002, 16.5884)
  line L6 (-13.3002, -15.6616) -> (13.3002, -15.6616)
  line L7 (-13.3002, 16.5884) -> (-13.3002, -15.6616)
  line L8 (-13.3, 16.5884) -> (-13.3002, 16.5884)
  line L9 (-13.3, 87.5884) -> (-13.3, 16.5884)
  line L10 (13.3, 87.5884) -> (-13.3, 87.5884)
  line L11 (13.3, 16.5884) -> (13.3, 87.5884)
  line L12 (13.3002, 16.5884) -> (13.3, 16.5884)
  line L13 (-13.3, 32.3184) -> (-13.3, 35.2584)
  line L14 (-13.3, 38.2584) -> (-13.3, 35.2584)
  line L15 (-16.7262, 38.2584) -> (-13.3, 38.2584)
  line L16 (-13.3, 29.3184) -> (-13.3, 32.3184)
  line L17 (-16.7262, 29.3184) -> (-13.3, 29.3184)
  arc A1 centre (-11.7262, 84.5884) radius 5 clockwise from (-16.7262, 84.5884) to (-11.7262, 89.5884)
  arc A2 centre (-11.7262, -12.4116) radius 5 clockwise from (-11.7262, -17.4116) to (-16.7262, -12.4116)
  arc A3 centre (11.7262, -12.4116) radius 5 clockwise from (16.7262, -12.4116) to (11.7262, -17.4116)
  arc A4 centre (11.7262, 84.5884) radius 5 clockwise from (11.7262, 89.5884) to (16.7262, 84.5884)
  point P24 (-13.3, 35.2584)
  point P25 (-13.3, 38.2584)
  point P27 (-13.3, 32.3184)
  point P28 (-13.3, 29.3184)
  dimension "d327" distance P24 P25 = 3
  dimension "d328" distance P27 P28 = 3
extrude "Extrude42" cut sketch "Sketch13" profile of A1 L1 A2 L2 A3 L3 A4 L4 L5 L6 L7 L8 L9 L10 L11 L12 L15 L17 against normal blind 5
extrude "Extrude43" add of existing geometry blind 1
position "Position4"
extrude "Extrude44" add of existing geometry to an object
sketch "Sketch14" plane through (-13.3002, 0, 0) normal (1, 0, 0) x axis (0, 1, 0)
  line L1 (-83.6325, -15.6616) -> (-83.6325, -9.5116)
  line L2 (-82.1325, -15.6616) -> (-83.6325, -15.6616)
  line L3 (-82.1325, 16.5884) -> (-82.1325, -15.6616)
  line L4 (-83.6325, 16.5884) -> (-82.1325, 16.5884)
  line L5 (-83.6325, 10.4884) -> (-83.6325, 16.5884)
  line L6 (-90.5825, 10.4884) -> (-83.6325, 10.4884)
  line L7 (-90.5825, 16.5884) -> (-90.5825, 10.4884)
  line L8 (-100.6325, 16.5884) -> (-90.5825, 16.5884)
  line L9 (-100.6325, -15.6616) -> (-100.6325, 16.5884)
  line L10 (-90.5825, -15.6616) -> (-100.6325, -15.6616)
  line L11 (-90.5825, -9.5116) -> (-90.5825, -15.6616)
  line L12 (-83.6325, -9.5116) -> (-90.5825, -9.5116)
  line L13 (-83.6325, 10.4884) -> (-83.6325, -9.5116)
  line L14 (-83.6325, 19.3384) -> (-83.6325, 16.5884)
  line L15 (-82.1325, 19.3384) -> (-83.6325, 19.3384)
  line L16 (-82.1325, -15.6616) -> (-82.1325, 19.3384)
  dimension "d338" distance L2 L15 = 35
extrude "Extrude45" cut sketch "Sketch14" profile of L1 L2 L3 L4 L5 L13 L14 L15 L16 against normal blind 2
extrude "Extrude46" cut of existing geometry blind -2
sketch "Sketch15" plane through (0, -83.6325, 0) normal (0, 1, 0) x axis (-1, 0, 0)
  line L1 (7.83, -9.5116) -> (13.3002, -9.5116)
  line L2 (7.83, -15.6616) -> (7.83, -9.5116)
  line L3 (15.3002, -15.6616) -> (7.83, -15.6616)
  line L4 (15.3002, 19.3384) -> (15.3002, -15.6616)
  line L5 (13.3, 19.3384) -> (15.3002, 19.3384)
  line L6 (13.3, 16.5884) -> (13.3, 19.3384)
  line L7 (7.83, 16.5884) -> (13.3, 16.5884)
  line L8 (7.83, 10.4884) -> (7.83, 16.5884)
  line L9 (13.3002, 10.4884) -> (7.83, 10.4884)
  line L10 (13.3002, -9.5116) -> (13.3002, 10.4884)
  line L11 (11.5662, -5.6616) -> (11.5662, 8.8384)
  line L12 (11.5662, 1.5884) -> (11.5662, -5.6616)
  line L13 (15.3002, 1.5884) -> (11.5662, 1.5884)
  line L14 (15.3002, 8.0884) -> (13.3002, 8.0884)
  line L15 (15.3002, -5.0116) -> (13.3002, -5.0116)
  circle C1 centre (10.83, 13.4884) radius 1.55
  circle C2 centre (10.83, -12.5116) radius 1.55
  dimension "d344" distance L13 L15 = 6.6
extrude "Extrude47" cut sketch "Sketch15" profile of L4 L10 L13 L14 L15 against normal blind 11
fillet "Fillet1" radius 7.5
position "Position6"
position "Position7"
sketch "Sketch3" plane through (-16.7662, 0, 0) normal (-1, 0, 0) x axis (0, -1, 0)
  line L1 (67.8625, 104.12) -> (67.8625, 198.31)
  line L2 (71.1125, 104.12) -> (67.8625, 104.12)
  line L3 (71.1125, 108) -> (71.1125, 104.12)
  line L4 (84.5625, 108) -> (71.1125, 108)
  line L5 (84.5625, 198.31) -> (84.5625, 108)
  line L6 (67.8625, 198.31) -> (84.5625, 198.31)
  line L7 (84.5625, 145.66) -> (67.8625, 145.66)
  line L8 (84.5625, 0) -> (84.5625, 145.66)
  line L9 (67.8625, 0) -> (84.5625, 0)
  line L10 (67.8625, 145.66) -> (67.8625, 0)
  line L11 (67.8625, 16.7) -> (36.55, 16.7)
  line L12 (67.8625, 0) -> (67.8625, 16.7)
  line L13 (36.55, 0) -> (67.8625, 0)
  line L14 (36.55, 16.7) -> (36.55, 0)
  line L15 (78.09, 0) -> (-16.1, 0)
  line L16 (78.09, 3.25) -> (78.09, 0)
  line L17 (74.21, 3.25) -> (78.09, 3.25)
  line L18 (74.21, 16.7) -> (74.21, 3.25)
  line L19 (-16.1, 16.7) -> (74.21, 16.7)
  line L20 (-16.1, 0) -> (-16.1, 16.7)
  line L21 (-16.1, 0) -> (78.09, 0)
  line L22 (-16.1, 16.7) -> (-16.1, 0)
  line L23 (74.21, 16.7) -> (-16.1, 16.7)
  line L24 (74.21, 3.25) -> (74.21, 16.7)
  line L25 (78.09, 3.25) -> (74.21, 3.25)
  line L26 (78.09, 0) -> (78.09, 3.25)
  line L27 (47.05, 3.9006) -> (41.05, 3.9006)
  line L28 (41.05, 7.7006) -> (47.05, 7.7006)
  line L29 (47.05, 5.8006) -> (41.05, 5.8006)
  line L30 (70.9994, 5.8006) -> (44.05, 5.8006)
  line L31 (57.5247, 12) -> (57.5247, 5.8006)
  line L32 (73.9994, 7.7006) -> (67.9994, 7.7006)
  line L33 (67.9994, 3.9006) -> (73.9994, 3.9006)
  line L34 (84.5625, 100.24) -> (81.5625, 100.24)
  line L35 (67.8625, 100.24) -> (70.8625, 100.24)
  line L36 (81.5625, 100.24) -> (86.82, 100.24)
  line L37 (81.5625, 100.24) -> (70.8625, 100.24)
  line L38 (81.5625, 100.24) -> (81.5625, 41.8988)
  line L39 (70.8625, 41.8988) -> (70.8625, 100.24)
  circle C1 centre (81.5625, 111.2106) radius 1.4
  circle C2 centre (73.6631, 168.3606) radius 1.4
  circle C3 centre (73.6631, 138.16) radius 1.4
  circle C4 centre (81.5625, 138.16) radius 1.4
  circle C5 centre (81.5625, 168.3606) radius 1.4
  circle C6 centre (81.5625, 195.31) radius 1.4
  circle C7 centre (73.6631, 111.2106) radius 1.4
  circle C8 centre (73.6631, 195.31) radius 1.4
  circle C9 centre (70.9994, 5.8006) radius 1.4
  circle C10 centre (44.05, 5.8006) radius 1.4
  circle C11 centre (44.05, 5.8006) radius 1.4
  circle C12 centre (70.9994, 13.7) radius 1.4
  circle C13 centre (13.8494, 5.8006) radius 1.4
  circle C14 centre (44.05, 5.8006) radius 1.4
  circle C15 centre (44.05, 13.7) radius 1.4
  circle C16 centre (13.8494, 13.7) radius 1.4
  circle C17 centre (-13.1, 13.7) radius 1.4
  circle C18 centre (70.9994, 5.8006) radius 1.4
  circle C19 centre (-13.1, 5.8006) radius 1.4
  circle C20 centre (-13.1, 5.8006) radius 1.4
  circle C21 centre (70.9994, 5.8006) radius 1.4
  circle C22 centre (70.9994, 13.7) radius 1.4
  circle C23 centre (-13.1, 13.7) radius 1.4
  circle C24 centre (44.05, 13.7) radius 1.4
  circle C25 centre (13.8494, 13.7) radius 1.4
  circle C26 centre (44.05, 5.8006) radius 1.4
  circle C27 centre (13.8494, 5.8006) radius 1.4
  arc A1 centre (47.05, 5.8006) radius 1.9 clockwise from (47.05, 7.7006) to (47.05, 3.9006)
  arc A2 centre (41.05, 5.8006) radius 1.9 clockwise from (41.05, 3.9006) to (41.05, 7.7006)
  arc A3 centre (67.9994, 5.8006) radius 1.9 clockwise from (67.9994, 3.9006) to (67.9994, 7.7006)
  arc A4 centre (73.9994, 5.8006) radius 1.9 clockwise from (73.9994, 7.7006) to (73.9994, 3.9006)
  circle C28 centre (73.6631, 138.16) radius 1.9
  circle C29 centre (73.6631, 111.2106) radius 1.9
  circle C30 centre (70.8625, 100.24) radius 1.625
  circle C31 centre (81.5625, 100.24) radius 1.625
  circle C32 centre (86.82, 100.24) radius 1.47
  circle C33 centre (70.8625, 41.8988) radius 1.625
  circle C34 centre (80.12, 51.2) radius 1.47
  circle C35 centre (81.5625, 41.8988) radius 1.625
  point P58 (41.05, 5.8006)
  point P59 (47.05, 5.8006)
  point P76 (70.8625, 100.24)
  point P77 (67.8625, 100.24)
  point P75 (84.5625, 100.24)
  point P84 (81.5625, 100.24)
  point P60 (44.05, 5.8006)
  point P70 (73.6631, 138.16)
  dimension "d350" distance L27 L28 = 3.8
  dimension "d351" distance P58 P59 = 6
  dimension "d352" diameter C28 = 3.8
  dimension "d353" diameter C29 = 3.8
  dimension "d361" diameter C30 = 3.25
  dimension "d363" diameter C31 = 3.25
  dimension "d364" distance L8 L10 = 16.7
  dimension "d372" diameter C33 = 3.25
  dimension "d373" diameter C35 = 3.25
  dimension "d374" distance P76 P77 = 3
  dimension "d375" distance P75 P84 = 3
  dimension "d380" distance L14 P60 = 7.5
  dimension "d381" distance L7 P70 = 7.5
position "Position9" RotateAboutZ -50
position "Position8" RotateAboutZ 0
sketch "Sketch6" plane through (0, 0, 0) normal (0, -1, 0) x axis (1, 0, 0)
  line L1 (0, 0) -> (-52, 0)
  line L2 (0, 107) -> (0, 0)
  line L3 (-52, 107) -> (0, 107)
  line L4 (-52, 0) -> (-52, 107)
  line L5 (-8.15, 23.32) -> (-19.15, 23.32)
  line L6 (-8.15, 12.32) -> (-8.15, 23.32)
  line L7 (-19.15, 12.32) -> (-8.15, 12.32)
  line L8 (-19.15, 23.32) -> (-19.15, 12.32)
  point P7 (-8.15, 23.32)
  point P8 (-8.15, 12.32)
  point P9 (-19.15, 12.32)
  dimension "d355" distance L1 L7 = 12.32
  dimension "d356" distance P7 P8 = 11
  dimension "d357" distance L2 L6 = 8.15
  dimension "d358" distance P8 P9 = 11
extrude "Extrude5" new body sketch "Sketch6" profile of L5 L6 L7 L8 along a picked direction blind 35
position "Position10"
sketch "Sketch16" plane through (0, 0, 89.5884) normal (0, 0, 1) x axis (-1, 0, 0)
  line L1 (11.7262, 82.1325) -> (-11.7262, 82.1325)
  line L2 (11.7262, 99.6325) -> (11.7262, 82.1325)
  line L3 (-11.7262, 99.6325) -> (11.7262, 99.6325)
  line L4 (-11.7262, 82.1325) -> (-11.7262, 99.6325)
  line L5 (0, 82.1325) -> (0, 99.6325)
  line L6 (-3, 82.1339) -> (0, 82.1325)
  line L7 (2.9998, 82.1672) -> (0, 82.1325)
  line L8 (-3.0036, 86.1338) -> (-3, 82.1339)
  line L9 (2.9538, 86.1392) -> (-3.0036, 86.1338)
  line L10 (2.9998, 82.1672) -> (2.9538, 86.1392)
  point P7 (0, 82.1325)
  point P8 (-3, 82.1339)
  point P9 (2.9998, 82.1672)
  point P10 (-3.0036, 86.1338)
  dimension "d365" distance P7 P8 = 3
  dimension "d366" distance P7 P9 = 3
  dimension "d367" distance P8 P10 = 4
extrude "Extrude2" sketch "Sketch3" profile of C1 C4 L1 L2 L3 L4 L5 L7 L8 L9 L10 L11 L12 L13 L14 C12 C15 L15 L16 L17 L18 L19 C22 C24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 blind 4.7625
fillet "Fillet1" radius 3
fillet "Fillet2" radius 10
fillet "Fillet3" radius 3
fillet "Fillet4" radius 3
position "Position11" RotateAboutZ -50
